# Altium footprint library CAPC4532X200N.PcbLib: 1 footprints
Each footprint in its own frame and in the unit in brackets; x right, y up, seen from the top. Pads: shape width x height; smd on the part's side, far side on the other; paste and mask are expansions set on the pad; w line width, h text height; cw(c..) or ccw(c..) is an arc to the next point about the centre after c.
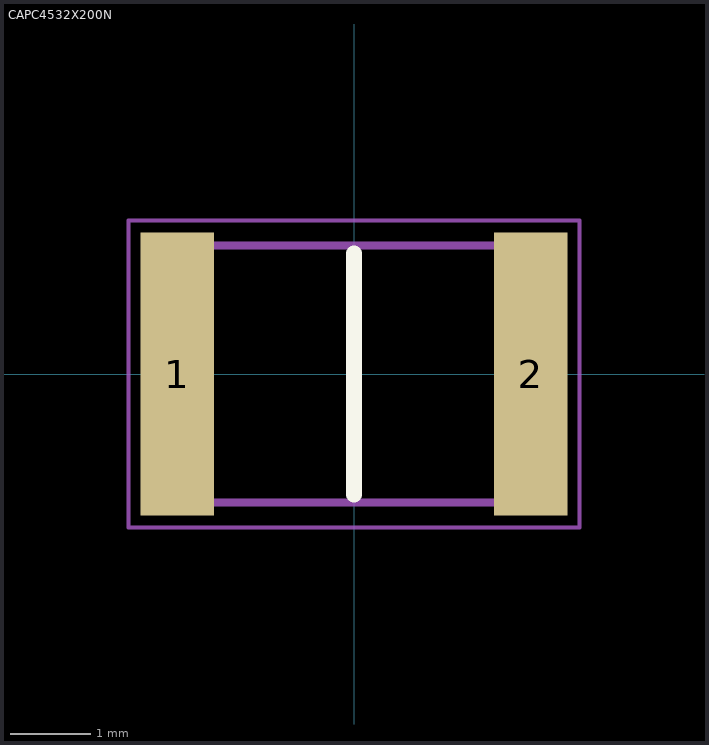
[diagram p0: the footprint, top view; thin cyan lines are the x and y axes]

## CAPC4532X200N [mm]
pads (2):
  rect 0.91x3.52 smd: 1(-2.2,0) 2(2.2,0)
Top Overlay:
  lines w0.2: 0,-1.5 0,1.5
Mechanical 15:
  lines w0.1: -2.25,-1.6 2.25,-1.6 2.25,1.6 -2.25,1.6 -2.25,-1.6
Mechanical 20:
  lines w0.05: -2.805,-1.91 2.805,-1.91 2.805,1.91 -2.805,1.91 -2.805,-1.91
